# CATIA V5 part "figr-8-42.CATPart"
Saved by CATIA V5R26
Part number: Part1
Bounding box of the stored display mesh (mm): x -75 to 75, y -75 to 75, z 0 to 20
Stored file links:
  D:\_Deepak\CATIA\CATIA V5-6R2016_Deepak\Resources\Part files\Partfiles\c08_catia_v5_6r2016_prt\figr-8-42.CATPart
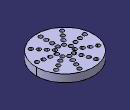
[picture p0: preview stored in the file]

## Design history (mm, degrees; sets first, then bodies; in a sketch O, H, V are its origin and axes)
Body1 (main body)
  Sketch1 on xy-plane, origin (0, 0, 0), H (1, 0, 0), V (0, 1, 0)
    circle A1 centre (0, 0) radius 75
    point P1 (75, 0)
    radius A1 = 75
    coincidence: A1 P1, P1 H
  Pad1: profile Sketch1, direction (0, 0, 1), length 20
  Sketch2 on face of Pad1, origin (0, 0, 20), H (1, 0, 0), V (0, 1, 0)
    circle A1 centre (0, -18.7232) radius 5.1678
    point P1 (0, -18.7232)
    coincidence: P1 V
  Pocket1: profile Sketch2, direction (0, 0, -1), through (limit type 3)
  CircPattern1: of Pocket1, instances 9, angular step 40 {= 360.0*1 deg/CircPattern1.AngularNumber}, circles 4, radial step 15, axis from face of Pad1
